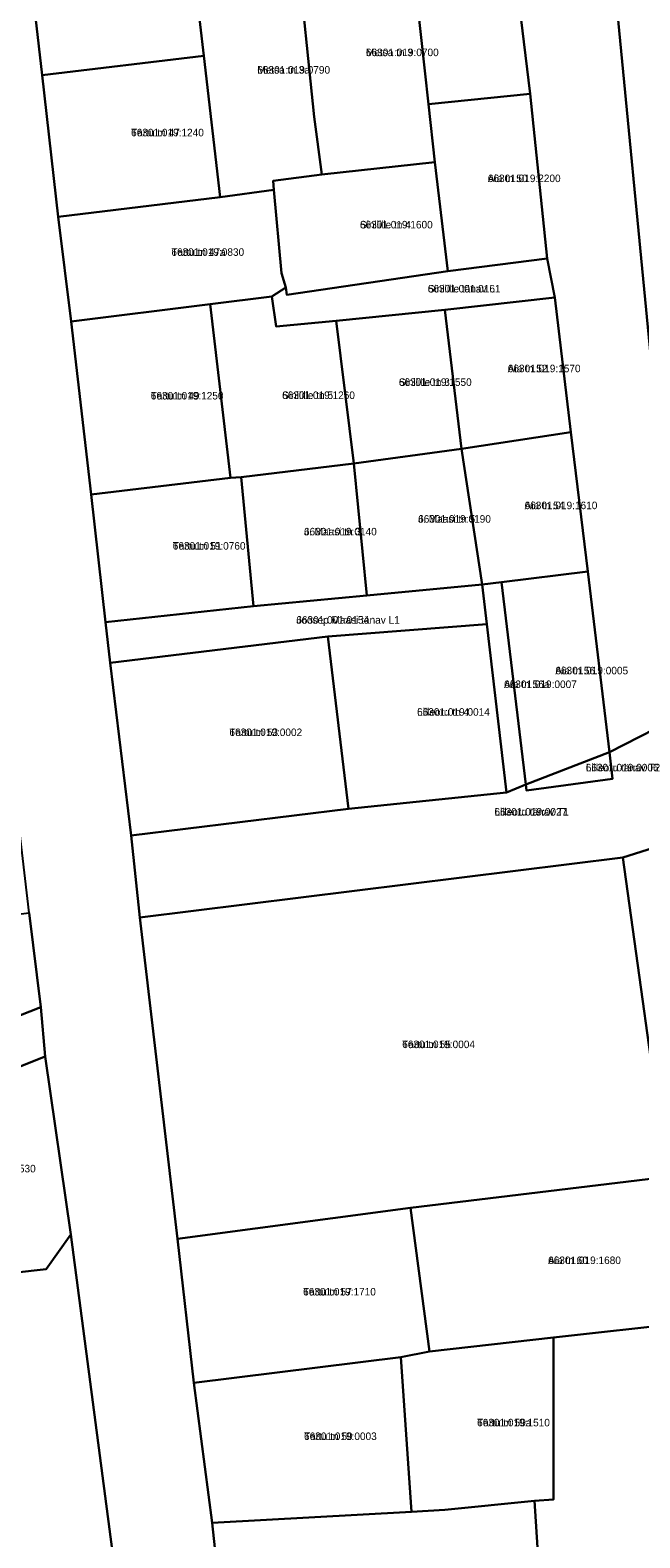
# Model space of a CAD drawing. Extents: x 632278 to 636344, y 6578401 to 6583362.
# Drawn here: x 634526.9 to 634648.4, y 6578915.6 to 6579215.9 of the extents above; entities that cross this region are included whole.
import ezdxf

# ---------------------------------------------------------------- set-up
doc = ezdxf.new("R2010")
doc.units = 0
for name, color, linetype in [('L_AADRESS', 7, 'Continuous'), ('PIIR', 7, 'Continuous'), ('TUNNUS', 7, 'Continuous')]:
    doc.layers.add(name, color=color, linetype=linetype)

msp = doc.modelspace()

# ---------------------------------------------------------------- linework, layer by layer
at = {"layer": 'PIIR'}
for points in [[(634683.61, 6578861.97), (634681.47, 6578962.07), (634668.96, 6578959.68), (634659.72, 6579055.77), (634657.39, 6579079.77), (634640.69, 6579253.02), (634619.84, 6579395.9), (634646.99, 6579406.93), (634634.13, 6579438.99), (634626.39, 6579457.25), (634762.59, 6579522.66), (634923.65, 6579631.25), (634921.5, 6579637.56), (634910.69, 6579669.18), (634900.72, 6579698.39), (634889.72, 6579730.89), (634877.71, 6579767.04), (634867.15, 6579797.74), (634863.84, 6579807.62), (634853.17, 6579839.67), (634843.13, 6579869.84), (634827.14, 6579901.97), (634840.49, 6579911.35)], [(634606.07, 6579427.5), (634619.84, 6579395.9), (634640.69, 6579253.02), (634657.39, 6579079.77), (634642.31, 6579072.08), (634637.99, 6579108.05), (634634.64, 6579135.86), (634631.42, 6579162.67), (634629.92, 6579170.43), (634626.53, 6579203.23), (634622.48, 6579236.56), (634621.08, 6579251.12), (634617.91, 6579278.62), (634614.75, 6579306.11), (634613.83, 6579314.07), (634610.67, 6579341.56), (634607.5, 6579369.06), (634605.71, 6579376.95), (634603.2, 6579388.09), (634600.67, 6579395.5), (634584.49, 6579440.21)], [(634527.1, 6579226.08), (634529.28, 6579206.94), (634532.5, 6579178.71), (634535.06, 6579157.85), (634539.08, 6579123.4), (634541.93, 6579097.97), (634542.87, 6579089.89), (634547.03, 6579055.47), (634548.76, 6579039.12), (634556.29, 6578975.14), (634559.53, 6578946.41), (634563.21, 6578918.53), (634569.36, 6578860.65)], [(634543.25, 6578913.24), (634535.03, 6578975.98), (634529.91, 6579011.46), (634529.03, 6579021.28), (634526.73, 6579040.08), (634525, 6579054.86), (634522.53, 6579076.48), (634520.17, 6579098.37), (634515.17, 6579141.25), (634492.19, 6579138.02), (634485.52, 6579130.52), (634485.07, 6579136.63), (634491.36, 6579143.31), (634514.46, 6579146.31), (634512.19, 6579164.63), (634509.88, 6579183.14), (634505.1, 6579223.6)], [(634569.36, 6578860.65), (634563.21, 6578918.53), (634602.91, 6578920.73), (634609.53, 6578921.13), (634627.38, 6578922.96), (634631.31, 6578862.01)]]:
    msp.add_lwpolyline(points, dxfattribs=at)
for points in [[(634602.6, 6579234.42), (634622.48, 6579236.56), (634626.53, 6579203.23), (634606.27, 6579201.17)], [(634602.6, 6579234.42), (634606.27, 6579201.17), (634607.51, 6579189.63), (634585.04, 6579187.19), (634583.48, 6579198.62), (634580.11, 6579231.66)], [(634527.1, 6579226.08), (634559.3, 6579229.61), (634561.49, 6579210.83), (634529.28, 6579206.94)], [(634561.49, 6579210.83), (634559.3, 6579229.61), (634580.11, 6579231.66), (634583.48, 6579198.62), (634585.04, 6579187.19), (634575.35, 6579185.93), (634575.47, 6579184.08), (634564.78, 6579182.65)], [(634529.28, 6579206.94), (634561.49, 6579210.83), (634564.78, 6579182.65), (634532.5, 6579178.71)], [(634607.51, 6579189.63), (634606.27, 6579201.17), (634626.53, 6579203.23), (634629.92, 6579170.43), (634610.1, 6579167.9)], [(634577.86, 6579164.62), (634576.96, 6579167.52), (634575.47, 6579184.08), (634575.35, 6579185.93), (634585.04, 6579187.19), (634607.51, 6579189.63), (634610.1, 6579167.9), (634578.03, 6579163.22)], [(634532.5, 6579178.71), (634564.78, 6579182.65), (634575.47, 6579184.08), (634576.96, 6579167.52), (634577.86, 6579164.62), (634575.07, 6579162.85), (634562.81, 6579161.32), (634535.06, 6579157.85)], [(634575.07, 6579162.85), (634577.86, 6579164.62), (634578.03, 6579163.22), (634610.1, 6579167.9), (634629.92, 6579170.43), (634631.42, 6579162.67), (634609.51, 6579160.17), (634587.9, 6579158.03), (634575.92, 6579156.89)], [(634535.06, 6579157.85), (634562.81, 6579161.32), (634566.81, 6579126.76), (634539.08, 6579123.4)], [(634566.81, 6579126.76), (634562.81, 6579161.32), (634575.07, 6579162.85), (634575.92, 6579156.89), (634587.9, 6579158.03), (634591.42, 6579129.62), (634568.94, 6579126.89)], [(634587.9, 6579158.03), (634609.51, 6579160.17), (634612.85, 6579132.54), (634591.42, 6579129.62)], [(634609.51, 6579160.17), (634631.42, 6579162.67), (634634.64, 6579135.86), (634612.85, 6579132.54)], [(634617, 6579105.46), (634612.85, 6579132.54), (634634.64, 6579135.86), (634637.99, 6579108.04), (634620.79, 6579105.98)], [(634591.42, 6579129.62), (634612.85, 6579132.54), (634617, 6579105.46), (634594.01, 6579103.28)], [(634571.4, 6579101.19), (634568.94, 6579126.89), (634591.42, 6579129.62), (634594.01, 6579103.28)], [(634539.08, 6579123.4), (634566.81, 6579126.76), (634568.94, 6579126.89), (634571.4, 6579101.19), (634541.93, 6579097.97)], [(634620.79, 6579105.98), (634625.66, 6579065.64), (634621.82, 6579064.03), (634617.9, 6579097.56), (634617, 6579105.46)], [(634620.79, 6579105.98), (634637.99, 6579108.04), (634642.31, 6579072.08), (634625.66, 6579065.64)], [(634541.93, 6579097.97), (634571.4, 6579101.19), (634594.01, 6579103.28), (634617, 6579105.46), (634617.9, 6579097.56), (634586.19, 6579095.12), (634542.87, 6579089.89)], [(634586.19, 6579095.12), (634617.9, 6579097.56), (634621.82, 6579064.03), (634590.34, 6579060.78)], [(634542.87, 6579089.89), (634586.19, 6579095.12), (634590.34, 6579060.78), (634547.03, 6579055.47)], [(634642.94, 6579066.8), (634642.31, 6579072.08), (634657.39, 6579079.77), (634659.72, 6579055.77), (634644.99, 6579051.1), (634548.76, 6579039.12), (634547.03, 6579055.47), (634590.34, 6579060.78), (634621.82, 6579064.03), (634625.66, 6579065.64), (634625.8, 6579064.45)], [(634642.31, 6579072.08), (634642.94, 6579066.8), (634625.8, 6579064.45), (634625.66, 6579065.64)], [(634644.99, 6579051.1), (634659.72, 6579055.77), (634668.96, 6578959.68), (634657.54, 6578958.41), (634653.8, 6578987.5)], [(634548.76, 6579039.12), (634644.99, 6579051.1), (634653.8, 6578987.5), (634602.68, 6578981.27), (634556.29, 6578975.14)], [(634485.21, 6579034.95), (634526.73, 6579040.08), (634529.03, 6579021.28), (634493.92, 6579007.47)], [(634435.73, 6578984.41), (634466.96, 6578996.86), (634493.92, 6579007.47), (634529.03, 6579021.28), (634529.91, 6579011.46), (634492.76, 6578996.74), (634464.84, 6578985.97), (634437.02, 6578975.01)], [(634492.76, 6578996.74), (634529.91, 6579011.46), (634535.03, 6578975.98), (634530.1, 6578969.11), (634509.9, 6578966.8), (634496.64, 6578965.27)], [(634602.68, 6578981.27), (634653.8, 6578987.5), (634657.54, 6578958.41), (634631.17, 6578955.47), (634606.51, 6578952.69)], [(634556.29, 6578975.14), (634602.68, 6578981.27), (634606.51, 6578952.69), (634600.76, 6578951.57), (634559.53, 6578946.41)], [(634488.67, 6578894.11), (634479.96, 6578921.23), (634475.15, 6578919.72), (634473.89, 6578923.39), (634465.01, 6578952.32), (634469.26, 6578954.36), (634496.64, 6578965.27), (634509.9, 6578966.8), (634530.1, 6578969.11), (634535.03, 6578975.98), (634543.25, 6578913.24), (634536.98, 6578905.9), (634490.39, 6578888.57)], [(634681.47, 6578962.07), (634683.61, 6578861.97), (634631.31, 6578862.01), (634627.38, 6578922.96), (634631.17, 6578923.2), (634631.17, 6578955.47), (634657.54, 6578958.41), (634668.96, 6578959.68)], [(634602.91, 6578920.73), (634600.76, 6578951.57), (634606.51, 6578952.69), (634631.17, 6578955.47), (634631.17, 6578923.2), (634627.38, 6578922.96), (634609.53, 6578921.13)], [(634559.53, 6578946.41), (634600.76, 6578951.57), (634602.91, 6578920.73), (634563.21, 6578918.53)]]:
    msp.add_lwpolyline(points, close=True, dxfattribs=at)

# ---------------------------------------------------------------- texts
at = {"layer": 'L_AADRESS'}
for s, p in [('Metsa tn 3', (634593.81, 6579210.74)), ('Metsa tn 3a', (634572.17, 6579207.26)), ('Tartu tn 47', (634547.02, 6579194.77)), ('Aia tn 50', (634618.1, 6579185.65)), ('Sinilille tn 4', (634592.62, 6579176.42)), ('Tartu tn 47a', (634555.05, 6579170.96)), ('Sinilille tänav L1', (634606.14, 6579163.66)), ('Aia tn 52', (634622.07, 6579147.77)), ('Sinilille tn 3', (634600.38, 6579145.05)), ('Tartu tn 49', (634550.94, 6579142.34)), ('Sinilille tn 5', (634577.12, 6579142.44)), ('Aia tn 54', (634625.42, 6579120.49)), ('J. Maasi tn 5', (634604.21, 6579117.8)), ('J. Maasi tn 3', (634581.47, 6579115.27)), ('Tartu tn 51', (634555.32, 6579112.43)), ('Joosep Maasi tänav L1', (634579.93, 6579097.68)), ('Aia tn 56', (634631.55, 6579087.59)), ('Aia tn 56a', (634621.33, 6579084.86)), ('Lilleoru tn 4', (634604, 6579079.34)), ('Tartu tn 53', (634566.61, 6579075.29)), ('Lilleoru tänav T2', (634637.61, 6579068.26)), ('Lilleoru tänav T1', (634619.41, 6579059.45)), ('Tartu tn 55', (634601.04, 6579013.12)), ('Aia tn 60', (634630.11, 6578970.1)), ('Tartu tn 57', (634581.29, 6578963.84)), ('Tartu tn 59a', (634615.96, 6578937.77)), ('Tartu tn 59', (634581.47, 6578935.05))]:
    msp.add_text(s, height=1.5, dxfattribs=at).set_placement(p)
at = {"layer": 'TUNNUS'}
for s, p in [('66301:019:0700', (634593.81, 6579210.74)), ('66301:019:0790', (634572.17, 6579207.26)), ('66301:019:1240', (634547.02, 6579194.77)), ('66301:019:2200', (634618.1, 6579185.65)), ('66301:019:1600', (634592.62, 6579176.42)), ('66301:019:0830', (634555.05, 6579170.96)), ('66301:001:0161', (634606.14, 6579163.66)), ('66301:019:1570', (634622.07, 6579147.77)), ('66301:019:1550', (634600.38, 6579145.05)), ('66301:019:1250', (634550.94, 6579142.34)), ('66301:019:1260', (634577.12, 6579142.44)), ('66301:019:1610', (634625.42, 6579120.49)), ('66301:019:0190', (634604.21, 6579117.8)), ('66301:019:0140', (634581.47, 6579115.27)), ('66301:019:0760', (634555.32, 6579112.43)), ('66301:001:0154', (634579.93, 6579097.68)), ('66301:019:0005', (634631.55, 6579087.59)), ('66301:019:0007', (634621.33, 6579084.86)), ('66301:019:0014', (634604, 6579079.34)), ('66301:019:0002', (634566.61, 6579075.29)), ('66301:019:0006', (634637.61, 6579068.26)), ('66301:019:0027', (634619.41, 6579059.45)), ('66301:019:0004', (634601.04, 6579013.12)), ('66301:019:0530', (634513.52, 6578988.37)), ('66301:019:1680', (634630.11, 6578970.1)), ('66301:019:1710', (634581.29, 6578963.84)), ('66301:019:1510', (634615.96, 6578937.77)), ('66301:019:0003', (634581.47, 6578935.05))]:
    msp.add_text(s, height=1.5, dxfattribs=at).set_placement(p)

doc.saveas('drawing.dxf')
